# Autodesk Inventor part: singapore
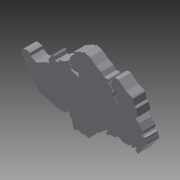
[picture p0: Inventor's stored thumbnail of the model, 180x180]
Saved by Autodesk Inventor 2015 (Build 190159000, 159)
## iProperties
Created: 2015-03
Part Number: singapore
Material: Generic
Document SubType Name: Modeling
Designer: User
Density: 1 g/cm^3
Appearance: Default
Author: User
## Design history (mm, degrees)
sketch "Sketch1"
  geometry: L1 (31.736, 36.613)-(29.262, 35.923); L2 (29.262, 35.923)-(26.922, 34.153); L3 (26.922, 34.153)-(24.923, 33.126); L4 (24.923, 33.126)-(23.79, 31.822); L5 (23.79, 31.822)-(22.428, 31.992); L6 (22.428, 31.992)-(22.002, 31.749); L7 (22.002, 31.749)-(22.117, 30.943); L8 (22.117, 30.943)-(20.01, 28.324); L9 (20.01, 28.324)-(19.896, 27.182); L10 (19.896, 27.182)-(18.381, 24.882); L11 (18.381, 24.882)-(18.076, 25.187); L12 (18.076, 25.187)-(18.187, 26.076); L13 (18.187, 26.076)-(18.93, 26.99); L14 (18.93, 26.99)-(18.93, 27.641); L15 (18.93, 27.641)-(18.1, 28.415); L16 (18.1, 28.415)-(19.715, 29.027); L17 (19.715, 29.027)-(21.043, 30.471); L18 (21.043, 30.471)-(20.295, 32.715); L19 (20.295, 32.715)-(19.659, 33.756); L20 (19.659, 33.756)-(18.671, 33.93); L21 (18.671, 33.93)-(17.974, 33.814); L22 (17.974, 33.814)-(14.892, 31.417); L23 (14.892, 31.417)-(12.955, 30.62); L24 (12.955, 30.62)-(12.259, 30.155); L25 (12.259, 30.155)-(11.632, 27.876); L26 (11.632, 27.876)-(10.833, 27.42); L27 (10.833, 27.42)-(10.256, 24.881); L28 (10.256, 24.881)-(10.559, 24.579); L29 (10.559, 24.579)-(11.445, 24.302); L30 (11.445, 24.302)-(11.235, 23.828); L31 (11.235, 23.828)-(9.812, 22.804); L32 (9.812, 22.804)-(8.266, 20.799); L33 (8.266, 20.799)-(8.149, 20.155); L34 (8.149, 20.155)-(8.485, 19.426); L35 (8.485, 19.426)-(8.171, 19.164); L36 (8.171, 19.164)-(7.124, 19.281); L37 (7.124, 19.281)-(7.124, 18.399); L38 (7.124, 18.399)-(6.781, 17.772); L39 (6.781, 17.772)-(6.781, 16.899); L40 (6.781, 16.899)-(10.103, 12.146); L41 (10.103, 12.146)-(10.119, 12.146); L42 (10.119, 12.146)-(10.358, 12.146); L43 (10.358, 12.146)-(11.359, 12.971); L44 (11.359, 12.971)-(10.792, 13.652); L45 (10.792, 13.652)-(11.2, 13.907); L46 (11.2, 13.907)-(12.283, 12.994); L47 (12.283, 12.994)-(12.772, 13.3); L48 (12.772, 13.3)-(12.772, 13.937); L49 (12.772, 13.937)-(13.7, 13.172); L50 (13.7, 13.172)-(16.515, 13.23); L51 (16.515, 13.23)-(17.371, 13.914); L52 (17.371, 13.914)-(19.103, 13.97); L53 (19.103, 13.97)-(19.274, 13.231); L54 (19.274, 13.231)-(21.285, 13.116); L55 (21.285, 13.116)-(22.496, 12.482); L56 (22.496, 12.482)-(23.045, 12.971); L57 (23.045, 12.971)-(22.265, 14.085); L58 (22.265, 14.085)-(22.88, 14.085); L59 (22.88, 14.085)-(24.237, 13.011); L60 (24.237, 13.011)-(24.866, 12.21); L61 (24.866, 12.21)-(26.518, 11.355); L62 (26.518, 11.355)-(27.429, 10.047); L63 (27.429, 10.047)-(28.57, 9.134); L64 (28.57, 9.134)-(29.722, 7.637)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; 1 further point
  constraints: 490 end point, 112 parallel, 25 perpendicular
  dimensions: "d2" = 50 horizontal distance of L159.end L39.end; "d3" = 28.97667 vertical distance of L1.start L64.end
extrude "Extrusion1" new body sketch "Sketch1" distance "d0" = 5; taper "d1" = 0 deg
body "Solid1"
